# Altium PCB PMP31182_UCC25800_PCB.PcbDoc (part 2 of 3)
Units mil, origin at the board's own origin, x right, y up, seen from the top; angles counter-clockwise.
Board outline 4922 x 2266 mil, 4 copper layers (Top Layer, Signal Layer 1, Signal Layer 2, Bottom Layer), stack 77.9 mil thick; 172 components, 94 nets, 533 pads, 516 vias.
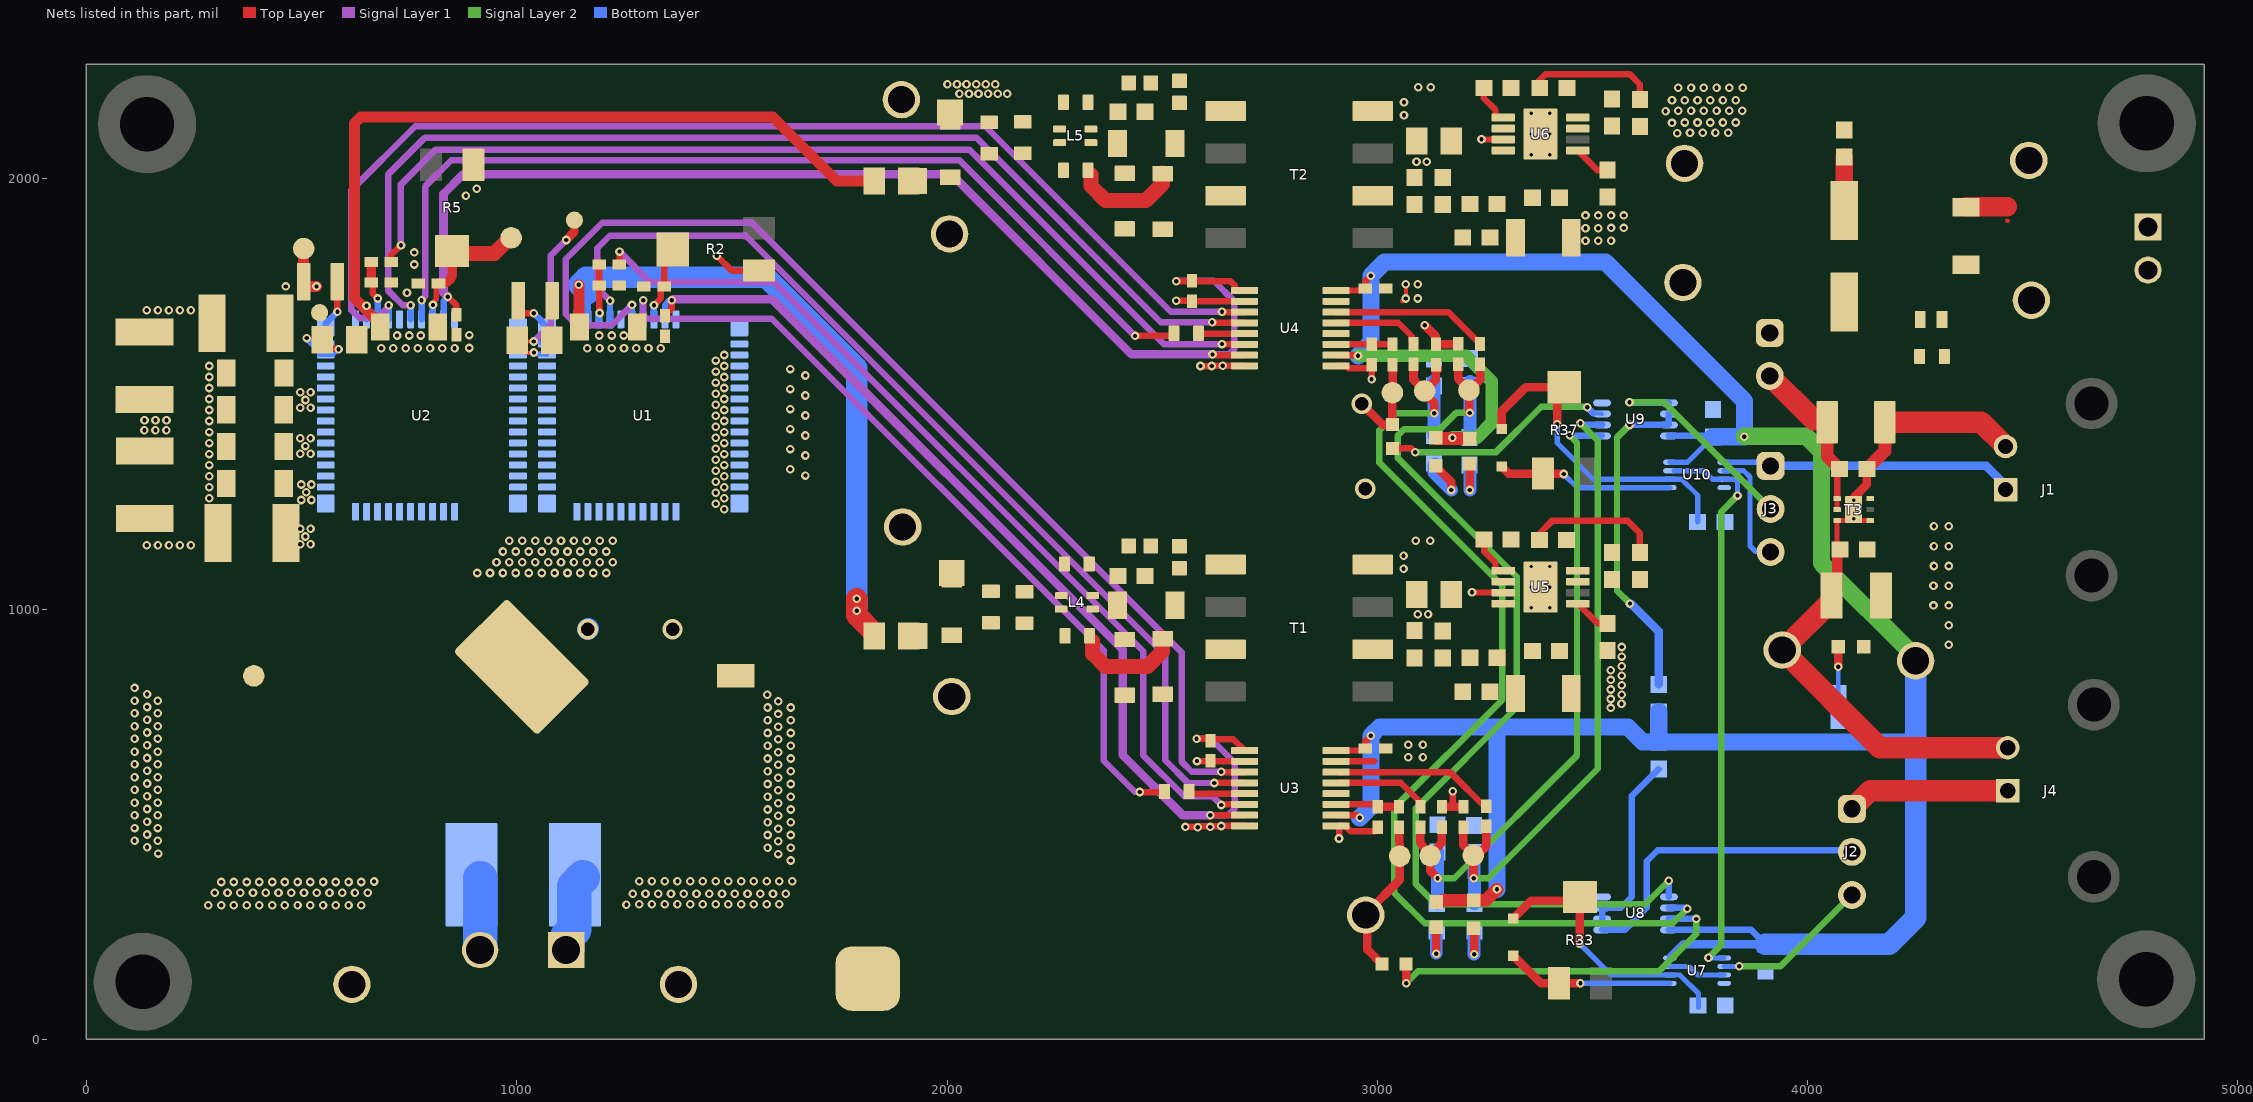
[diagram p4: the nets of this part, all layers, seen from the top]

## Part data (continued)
J7: library part CMP-0075405-2, "Header, 100mil, 2x1, Gold, TH", Color=Black, Current_A=6.3A, Manufacturer=Samtec, Supplier Part Number 1=SAM1029-02-ND, Voltage_V=550V
L1 L2: library part CMP-0090507-1, "4.7µH Shielded Molded Inductor 1.22A 262mOhm Max 1008 (2520 Metric)", Digikey Part Number=283-4799-1-ND, Manufacturer=Eaton, Mouser Part Number=704-MPIA2510V2-4R7-R, Operating Temperature Range="-40°C to +125°C", Self Resonant Frequency=25MHz, Test Frequency=1MHz, Tolerance_%=20%
L3: library part CMP-0060122-1, "Inductor, Wirewound, Ferrite, 240 nH, 0.85 A, 0.119999 ohm, SMD", Manufacturer=Coilcraft, PartNumber=0603AF-241KRB, Value1="0.119999 ohm", Value2=0.85A, ValueDisplayed=240nH
L4 L5: library part CMP-0090488-1, "2 Line Common Mode Choke Surface Mount 90 Ohms @ 100MHz 400mA DCR 190mOhm", Digikey Part Number=445-15969-1-ND, Impedance At Frequency="90Ω @ 100MHz", Manufacturer=TDK, Mouser Part Number=810-ACM20129002PT001, Operating Temperature Range="-40°C to +105°C"
LOGO1 LOGO3: library part CMP-0074837-1, "IEC 61010-1 Hot Surface Warning"
LOGO2 LOGO4: library part CMP-0074835-1, "IEC 61010-1 High Voltage Warning"
Logo6: library part CMP-0074838-1, "Texas Instrument Corporate Signature"
Logo8: library part CMP-0074769-1
R1 R3: library part CMP-0020443-3, "RES, 0, 5%, 0.333 W, AEC-Q200 Grade 0, 0805", Manufacturer=Vishay-Dale, Power_W=333mW, Supplier Part Number 1=541-0.0TBCT-ND, TempCo="200 ppm/C", Tolerance_%=5%, Value2=0.333W, Value_Code=0000, ValueDisplayed=0
R2 R5: library part CMP-0002064-2, "Trimmer, 200 K, 0.25 W, SMD", Manufacturer=Bourns, Supplier Part Number 1=3224X-1-204ECT-ND
R4 R8 R18 R26 R27 R41 R43: library part CMP-0089143-1, "0 Ohms Jumper 0.1W, 1/10W Chip Resistor 0603 (1608 Metric) Automotive AEC-Q200 Thick Film", Digikey Part Number=P0.0GCT-ND, Manufacturer=Panasonic, Mouser Part Number=667-ERJ-3GEY0R00V, Operating Temperature Range="-55°C to +155°C", Power_W=100mW, TempCo=-100/+600ppm/°C, Tolerance_%=5%
R6 R15 R19 R20 R39 R40: library part CMP-0026902-3, "RES, 300, 5%, 0.063 W, AEC-Q200 Grade 0, 0402", Manufacturer=Vishay-Dale, Power_W=63mW, Supplier Part Number 1=541-300JCT-ND, TempCo="200 ppm/C", Tolerance_%=5%, Value2=0.063W, Value_Code=300R, ValueDisplayed=300
R7 R16: library part CMP-0026404-2, "RES, 49.9, 1%, 0.063 W, AEC-Q200 Grade 0, 0402", Manufacturer=Vishay-Dale, Power_W=63mW, Supplier Part Number 1=541-49.9LCT-ND, TempCo="100 ppm/C", Tolerance_%=1%, Value2=0.063W, Value_Code=49R9, ValueDisplayed=49.9
R9 R24 R28 R32: library part CMP-0023630-3, "RES, 100 k, 0.1%, 0.1 W, 0603", Manufacturer="Yageo America", Power_W=100mW, Supplier Part Number 1=603-RT0603BRD07100KL, TempCo="25 ppm/C", Tolerance_%=0.1%, Value2=0.1W, Value_Code=100k
R10 R12 R14 R17 R21: library part CMP-0025797-4, "RES, 3.3 k, 5%, 0.1 W, AEC-Q200 Grade 0, 0603", Manufacturer=Vishay-Dale, Power_W=100mW, Supplier Part Number 1=541-3.3KGCT-ND, TempCo="200 ppm/C", Tolerance_%=5%, Value2=0.1W, Value_Code=3k30, ValueDisplayed=3.3k
R11 R29: library part CMP-0023990-3, "RES, 24.9 k, 0.1%, 0.1 W, 0603", Manufacturer="Yageo America", Power_W=100mW, TempCo="25 ppm/C", Tolerance_%=0.1%, Value2=0.1W, Value_Code=24k9, ValueDisplayed=24.9k
R13: library part CMP-0022714-3, "RES, 0.33, 1%, 0.1 W, AEC-Q200 Grade 0, 0603", Manufacturer=Panasonic, Power_W=100mW, Supplier Part Number 1=P.33AJCT-ND, TempCo="300 ppm/C", Tolerance_%=1%, Value2=0.1W, Value_Code=R330, ValueDisplayed=0.33
R22 R30: library part CMP-0024096-3, "RES, 30.1 k, 0.1%, 0.1 W, 0603", Manufacturer="Yageo America", Power_W=100mW, TempCo="25 ppm/C", Tolerance_%=0.1%, Value2=0.1W, Value_Code=30k1, ValueDisplayed=30.1k
R23 R31: library part CMP-0024954-2, "RES, 22.9 k, 0.5%, 0.1 W, 0603", Manufacturer="Yageo America", Power_W=100mW, TempCo="50 ppm/C", Tolerance_%=0.5%, Value2=0.1W, Value_Code=22k9, ValueDisplayed=22.9k
R25 R42: library part CMP-0023343-3, "RES, 0, 1%, 0.1 W, AEC-Q200 Grade 0, 0603", Manufacturer="Stackpole Electronics Inc", Power_W=100mW, Supplier Part Number 1=RMCF0603ZT0R00CT-ND, TempCo=ppm/C, Tolerance_%=1%, Value2=0.1W, Value_Code=0
R33 R37: library part CMP-0002062-2, "Trimmer, 5 K, 0.25 W, SMD", Manufacturer=Bourns, Supplier Part Number 1=3224X-1-502ECT-ND
R34 R38: library part CMP-0025697-4, "RES, 0, 5%, 0.1 W, AEC-Q200 Grade 0, 0603", Manufacturer=Vishay-Dale, Power_W=100mW, Supplier Part Number 1=541-0.0GCT-ND, TempCo="200 ppm/C", Tolerance_%=5%, Value2=0.1W, Value_Code=0000, ValueDisplayed=0
R35 R36: library part CMP-0082530-1, "RES, 100 k, 5%, 0.1 W, 0603", Manufacturer=Vishay-Dale, Power_W=100mW, Supplier Part Number 1=541-3992-1-ND, TempCo="200 ppm/C", Tolerance_%=5%, Value2=0.1W, Value_Code=100k
SH-J1 SH-J2 SH-J3: library part CMP-0003623-3, "Shunt, 100mil, Gold plated, Black", Alternate Manufacturer=3M, Alternate PartNumber=969102-0000-DA, Manufacturer=Samtec, Supplier Part Number 1=SAM8858-ND
T1 T2: library part CMP-0091345-1, "Transformer, 1:1.67, 0.045Ohm Pri, 0.122Ohm Sec, 16.5uH", Frequency_Fixed=500kHz, Manufacturer="Wurth Electronics", Operating Temperature Range="-40°C to +125°C", Part Number=750319177r02
T3: library part CMP-0086086-2, "150-mA High-Voltage Ultralow-IQ Low-Dropout Regulator, DRV0006A (WSON-6)", Alternate Manufacturer="Texas Instruments"
Top_FET_PWM: library part CMP-0055144-1, "Test Point, Compact, White, TH", Color=White, Manufacturer=Keystone, Supplier Part Number 1=36-5007-ND
TP1: library part CMP-0055153-1, "Test Point, Compact, SMT", Manufacturer=Keystone, Supplier Part Number 1=36-5016TR-ND
TP2: library part CMP-0003968-1, "Test Point, SMT", Manufacturer=Harwin, Supplier Part Number 1=952-2664-1-ND
U1 U2: library part CMP-0089968-1, "650-V 30-mΩ GaN FET with Integrated Driver and Protection", Manufacturer="Texas Instruments", Max Supply Voltage=18V, Min Supply Voltage=7.5V, Nominal Supply Current=540uA, Operating Temperature Range="-40°C to +125°C", Output Voltage=520V
U3 U4: library part CMP-0090469-1, "General Purpose Digital Isolator 2500Vrms 4 Channel 100Mbps 85kV/µs CMTI 16-SSOP (0.154\", 3.90mm Width)", Digikey Part Number=296-51207-1-ND, Manufacturer="Texas Instruments", Max Supply Voltage=5.5V, Min Supply Voltage=2.25V, Mouser Part Number=595-ISO7741FQDBQRQ1, Nominal Supply Current=1.5-18mA, Operating Temperature Range="-40°C to +125°C"
U5 U6: library part CMP-0088494-2, "Open Loop LLC Transformer Driver for Isolated Bias Supplies", Manufacturer="Texas Instruments", Max Supply Voltage=36V, Min Supply Voltage=12V, Nominal Supply Current=500uA, Operating Temperature Range="-40°C to +150°C", Switching Frequency=100-2000kHz
U7 U10: library part CMP-0051969-2, "Triple Schmitt-Trigger Inverter, DCU0008A (VSSOP-8)", F @ Nom Voltage(Max)(Mhz)=150, Generic Part Number=SN74LVC3G14, ICC @ Nom Voltage(Max)(mA)=0.01, Manufacturer="Texas Instruments", Operating Temperature Range="-40 to 125 C", Rating=Catalog, tpd @ Nom Voltage(Max)(ns)=9.2,5.7,5.4,4.3, Voltage(Nom)(V)=1.8,2.5,3.3,5
U8 U9: library part CMP-0051803-1, "Automotive Catalog Dual 2-Input Positive-AND Gate, DCT0008A, LARGE T&R", F @ Nom Voltage(Max)(Mhz)=150, Generic Part Number=SN74LVC2G08-Q1, ICC @ Nom Voltage(Max)(mA)=0.01, Manufacturer="Texas Instruments", Operating Temperature Range(C)="-40 to 85", Rating=Automotive, tpd @ Nom Voltage(Max)(ns)=9,5.1,4.7,3.8, Voltage(Nom)(V)=1.8,2.5,3.3,5

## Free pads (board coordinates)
  round 50 smd paste-30: 1(389,845) 1(505,1838) 1(987,1863) 1(3035,1503) 1(3052,426) 1(3110,1507) 1(3123,427) 1(3213,1509) 1(3223,428)
  round 40 smd paste-30: 1(542,1689) 1(1134,1904)
  round 228.35 hole 125.98: 2(131,134) 2(141,2127) 2(4787,140) 2(4788,2129)
  rect 60x60 smd: 3(1923,1995) 3(1925,938) 3(2007,2154) 3(2011,1084)
  rrect50% 150x150 smd: Load_GND(1816.25,141.5)

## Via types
v1: diameter 20, hole 10, Top Layer to Bottom Layer, tented both sides, 498 vias
v2: diameter 19.68, hole 7.87, Top Layer to Bottom Layer, 14 vias
v3: diameter 47.24, hole 31.5, Top Layer to Bottom Layer, 4 vias

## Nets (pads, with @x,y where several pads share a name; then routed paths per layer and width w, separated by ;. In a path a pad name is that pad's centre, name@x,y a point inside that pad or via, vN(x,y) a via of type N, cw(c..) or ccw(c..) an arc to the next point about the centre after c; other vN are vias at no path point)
5V: C9.1 C26.1 C41.2 C44.2 C48.1 C53.1 HS_FLT.1 HS_OC.1 LDO5V.1 LDO.1 LS_FLT.1 LS_OC.1 R35.1 R36.2 T3.6 U3.10 U3.16 U4.10 U4.16 U7.8 U8.8 U9.8 U10.8 | length 6821.8
  Top Layer w15: U3.10@2904.08,521.5 2952.5,521.5 v1(2959,515) ; U3.16@2904.08,671.5 2967.88,671.5 C26.1@2972.38,676 2972.38,693.38 v1(2985,706) ; U4.16@2904.33,1740.75 U4.16@2904.08,1740.5 2962.26,1740.5 C9.1@2969.57,1747.81 ; U4.10@2905.08,1590.5 2905.65,1589.93 2954.07,1589.93 v1(2955,1589) ; C9.1@2972.57,1744.81 2972.57,1762.57 v1(2985,1775)
  Top Layer w30: HS_FLT.1@3137,319.53 3137.75,320.28 3148.03,320.28 3151.24,323.48 HS_OC.1@3224,323.48 3252.48,323.48 v1(3278,349) ; LS_OC.1@3137.95,1396.53 v1@3172.57,1396.53 ; v1@3176.48,1396.53 LS_FLT.1@3215,1396.53
  Signal Layer 2 w30: v1@2956,1590 v1(2955,1589) 3206,1589 3266,1529 3266,1433 3231.48,1398.48 v1(3174.52,1398.48)
  Signal Layer 2 w40: v1(3853,1401) 3854,1402 3997,1402 4032,1367 4032,1107 4251,888 LDO5V.1@4251,880
  Bottom Layer w10: 4045.91,221.5 4045.91,221.65
  Bottom Layer w12: U10.8@3680.02,1341.37 3720.87,1341.37 C44.2@3780,1400.5
  Bottom Layer w15: U8.8@3677.76,254.61 3868.88,254.61 C41.2@3902,221.5 ; U9.8@3677.76,1402.61 C44.2@3777.89,1402.61
  Bottom Layer w20: R35.1@3654,693.5 3660.7,693.5 R35.1@3662.7,691.5 ; U7.8@3683.74,193.26 3711.98,221.5 C41.2@3902,221.5 ; 4245.5,691.5 4251,697
  Bottom Layer w40: v1(2955,1589) 2985,1619 v1(2985,1775) 3017,1807 3530,1807 3853,1484 v1(3853,1401) ; v1(2959,515) 2985,541 v1@2985,701.41 ; v1(2985,706) 3005,726 3278,726 ; v1(3278,349) 3278,726 ; R35.1@3654,691.5 3616.5,691.5 3582,726 3278,726 ; R35.1@3654,693.5 R36.2@3654,761.5 ; R35.1@3662.7,691.5 4245.5,691.5 ; C44.2@3780,1400.5 v1@3852.5,1400.5
  Bottom Layer w50: C41.2@3902,221.5 4045.91,221.5 4189.5,221.5 4251,283 4251,697 LDO5V.1@4251,880
  other v1: 4328,917.08 4328,962.91 4292.48,1008.75 4328,1008.75 4292.48,1054.58 4328,1054.58 4293.48,1100.41 4328,1100.41 4293.48,1146.46 4328,1146.46 4293.48,1192.46 4328,1192.46
5V_H: C2.1 C10.1 U1.51 U3.1 U3.7 | length 2474.7
  Top Layer w10: C10.1@2610.62,699 C10.1@2612,697.62
  Top Layer w15: C2.1@1344.59,1681.62 1344.59,1685.56 1348.9,1689.87 1351.67,1689.87 1360.45,1698.66 v1(1360.45,1718.06) ; v1(2580,699) C10.1@2610.62,699 ; C10.1@2612,697.62 2665.36,697.62 U3.1@2691.48,671.5 ; v1@2612.5,521.5 U3.7@2691.48,521.5
  Signal Layer 1 w15: v1(2580,699) 2613.08,699 2669,643.08 2669,537 2653,521 v1(2612,521)
  Signal Layer 1 w20: v1(1360.45,1718.06) 1362.37,1719.97 1369.44,1719.97 1594,1720 2408,906 2408,661 2548,521 v1(2612,521)
  Bottom Layer w15: U1.51@1344.59,1673.4 1344.59,1706.59 1355.1,1717.1 1359.5,1717.1 v1(1360.45,1718.06)
5V_L: C12.1 C27.1 U2.51 U4.1 U4.7 | length 2893.2
  Top Layer w15: v1(840,1726) 860,1706 C12.1@860,1684.62 ; v1(2533,1762) C27.1@2567.76,1762 ; C27.1@2573.5,1762 2658.7,1762 2669.13,1751.57 2669.13,1741.07 2669.7,1740.5 U4.1@2691.48,1740.5 ; v1(2617,1592) 2618.35,1592 2619.85,1590.5 U4.7@2691.48,1590.5
  Signal Layer 1 w15: v1@2533,1763 2620,1763 2668,1715 2668,1605.01 2654.99,1592 v1(2617,1592)
  Signal Layer 1 w20: v1(840,1726) 830,1736 830,1965 876,2011 2010,2011 2429,1592 v1(2617,1592)
  Bottom Layer w15: U2.51@830.17,1673.4 830.17,1716.17 v1(840,1726)
15V: 15VIN.1 C25.1 J6.2 L3.1 R8.1
15V_F: 15VINF.1 C7.1 C8.1 C24.1 C28.1 C29.1 C58.1 C59.1 C61.1 C62.1 J7.1 L3.2 R8.2 R9.2 R28.2 U5.8 U6.8
Bot_FET_FAULT: C52.1 C57.1 pad.1@3213,1509 R14.1 R40.2 U8.5 | length 2427.9
  Top Layer w20: C57.1@3188,1569.38 3188,1535.24 3204.07,1517.24 pad.1@3206.97,1514.34 ; pad.1@3213,1509 3214,1508 3214,1457 v1(3215,1456) ; pad.1@3215,1510.85 3239,1533 R40.2@3239,1569
  Signal Layer 2 w15: v1(3215,1456) 3183,1456 3145.49,1418.49 3062.49,1418.49 3047,1403 3047,1352 3324,1075 3324,772 3089,537 3089,361.5 3136.5,314 3622.38,314 v1@3677.19,368.81
  Bottom Layer w10: v1(3677,369) v1@3677.38,368.62 ; U8.5@3677.38,331.76 U8.5@3677.76,331.39
  Bottom Layer w15: U8.5@3677.38,331.76 v1@3677.38,368.62
  Bottom Layer w30: R14.1@3215,1398.5 v1(3215,1456) C52.1@3215,1529.5
Bot_FET_OC: C55.1 C56.1 pad.1@3110,1507 R17.1 R39.2 U8.6 | length 2553.9
  Top Layer w20: R39.2@3084,1569 3084,1533 pad.1@3110,1507 ; v1(3132,1455) 3132,1479.73 3110,1501.73 pad.1@3110,1507 ; C56.1@3140.7,1557.02 C56.1@3136,1568.38 3136,1533 pad.1@3110,1507
  Signal Layer 2 w15: v1(3132,1455) 3044,1455 3005,1416 3005,1340 3290,1055 3290,789 3039,538 3039,341 3110,270 3686,270 v1(3720,304)
  Bottom Layer w12: v1@3716.04,305.8 3717.84,304 v1(3720,304)
  Bottom Layer w15: U8.6@3677.76,305.8 v1@3716.04,305.8
  Bottom Layer w30: C55.1@3131,1530.5 3132,1529.5 v1(3132,1455) R17.1@3132,1403
Bot_FET_PWM: pad.1@3035,1503 R16.1 R38.2 | length 230.1
  Top Layer w20: v3(2964,1477) 3012,1429 R38.2@3035,1429 pad.1@3035,1503 3035.5,1537.5 R16.1@3035.5,1568.26
Bot_FET_TEMP: U4.12
FAULT_H: U1.46 U3.4 | length 2361.7
  Top Layer w10: U3.4@2705.23,595.25 U3.4@2706.48,596.5
  Top Layer w15: v1@2621.5,596.5 U3.4@2691.48,596.5
  Signal Layer 1 w15: v1(1217,1717) 1187,1747 1187,1839 1216,1868 1532,1868 2507,893 2507,649 2560,596 v1(2621,596)
  Bottom Layer w15: U1.46@1216.64,1673.4 1216.82,1673.58 1216.82,1712.82 v1@1217,1713
FAULT_L: U2.46 U4.3 | length 2734.9
  Top Layer w15: v1@2639.5,1690.5 U4.3@2691.48,1690.5
  Signal Layer 1 w15: v1(702.21,1706) 702.21,1704.65 699.71,1702.15 699.71,1700.07 675.65,1676 635,1676 616,1695 616,1974 764,2122 2089,2122 2520,1691 v1(2639,1691)
  Bottom Layer w15: U2.46@702.21,1673.4 v1(702.21,1706)
GND_HV: C11.1 C12.2 C13.1 C15.2 C16.2 C17.2 C18.2 C19.2 C20.2 C21.2 C23.1 C27.2 C38.2 C43.1 C49.2 C63.2 C64.2 D5.2 GNDHV.1 ISO15VGND.1 J5.1 L2.1 L5.1 pad.1@505,1838 pad.3@2007,2154 pad.Load_GND R5.1 R43.2 TP2.1 U2.17 U2.18 U2.19 U2.20 U2.21 U2.22 U2.23 U2.24 U2.25 U2.26 U2.27 U2.28 U2.29 U2.30 U2.31 U2.32 U2.33 U2.34 U2.35 U2.36 U2.37 U2.38 U2.39 U4.2 U4.8 | length 629.7
  Top Layer w10: C20.2@453,1138.74 C20.2@453,1159 ; pad.1@504.63,1834.63 pad.1@505,1835
  Top Layer w15: v1(2533,1717) C27.2@2562.19,1717 ; C27.2@2569.5,1715.5 U4.2@2691.48,1715.5 ; v1(2589,1565) v1(2615,1565) 2615.5,1565.5 2640.5,1565.5 v1(2641,1566) ; v1@2641.5,1565.5 U4.8@2691.48,1565.5
  Top Layer w25: pad.1@505,1835 504.63,1824.63 L2.1@504.63,1761 504.63,1750 v1(534.63,1750)
  Bottom Layer w10: C49.2@1109.47,344 C49.2@1148.47,383
  Bottom Layer w80: J5.1@1115,208 1117.32,210.32 1117.32,238.4 1133.57,254.64 1133.57,356.57 C49.2@1154,377
  other v1: 1255,313 1284.62,314 1314.23,314 1343.85,314 1373.46,314 1403.08,314 1432.69,314 1462.31,314 1491.92,314 1521.54,314 1551.15,314 1580.77,314 1610.38,314 1269.81,339 1299.42,339 1329.04,339 1358.65,339 1388.27,339 1417.88,339 1447.5,339 1477.11,339 1506.73,339 1536.34,339 1565.96,339 1595.57,339 1625.19,339 1284.62,368 1314.23,368 1343.85,368 1373.46,368 1403.08,368 1432.69,368 1462.31,368 1491.92,368 1521.54,368 1551.15,368 1580.77,368 1610.38,368 1640,368 1637,416 1608,430.81 1583,445.62 1637,445.62 1608,460.43 1583,475.23 1637,475.23 1608,490.04 1583,504.85 1637,504.85 1608,519.66 1583,534.46 1637,534.46 1608,549.27 1583,564.08 1637,564.08 1608,578.89 1583,593.69 1637,593.69 1608,608.5 1583,623.31 1637,623.31 1608,638.12 1583,652.92 1637,652.92 1608,667.73 1583,682.54 1637,682.54 1608,697.35 1583,712.15 1637,712.15 1608,726.96 1583,741.77 1637,741.77 1608,756.58 1583,771.38 1637,771.38 1608,786.19 1582,801 497,1150.87 521,1150.87 509,1168.87 497,1186.87 521,1186.87 499,1253.64 523,1253.64 511,1271.64 499,1289.64 523,1289.64 497,1361 521,1361 509,1379 497,1397 521,1397 134.82,1416 160.41,1416 186,1416 135,1439 160.59,1439 186.18,1439 497,1468 521,1468 509,1486 497,1504 521,1504 685,1606 713.43,1606 741.86,1606 770.29,1606 798.71,1606 827.14,1606 855.57,1606 890,1607 722,1636 750,1636 777,1636 890,1637 745,1735 463,1750 762,1801 762,1829 882,1961 907,1977 2028.84,2197.79 2051.04,2197.79 2073.24,2197.79 2095.44,2197.79 2117.64,2197.79 2139.84,2197.79 2001,2220 2023.2,2220 2045.4,2220 2067.6,2220 2089.8,2220 2112,2220
  other v3: 1362.2,953
GND_LV: C6.2 C7.2 C9.2 C14.1 C25.2 C26.2 C28.2 C29.2 C34.2 C36.2 C39.2 C40.2 C41.1 C44.1 C45.2 C46.2 C47.2 C48.2 C50.2 C51.2 C52.2 C53.2 C54.1 C55.2 C56.2 C57.2 C58.2 C61.2 C62.2 C67.2 C69.2 GND_LV.1 GNDLV.1 GNDLVF.1 J1.2 J4.2 J6.1 R13.1 R21.1 R22.1 R23.1 R24.1 R25.1 R30.1 R31.1 R32.1 R42.1 T3.3 T3.4 T3.7@4107,1231.35 U3.9 U3.15 U4.9 U4.15 U5.6 U5.9 U6.6 U6.9 U7.4 U8.4 U9.4 U10.4 | length 2933.8
  Top Layer w10: U3.9@2904.08,496.5 2907.93,496.5 U3.9@2911,493.43 ; C14.1@2986,1568.26 C14.1@2986.63,1567.63 ; C6.2@3001,489.56 C6.2@3001,493.5 ; 3057.8,1715.5 3064.29,1722 v1(3066,1722) 3067,1722 3066.5,1722.5 3066.5,1754.5 v1(3066,1755) ; 3175,543.97 3178.35,540.62 ; C48.2@4051.91,1035.63 C48.2@4055.91,1031.63 C48.2@4055.91,1019.91 ; C53.2@4068.61,1145.52 C53.2@4075.5,1138.63 ; T3.7@4103.06,1205.76 v2(4107,1209.69) T3.7@4110.94,1205.76 ; v2(4107,1253) T3.7@4113.95,1253 ; 4464.07,1902.93 4465,1902
  Top Layer w12: C53.2@4068.61,1145.52 T3.3@4068.61,1205.76 T3.7@4103.06,1205.76 ; T3.7@4110.94,1205.76 T3.4@4145.39,1205.76
  Top Layer w15: U3.15@2904.08,646.5 2993,646.5 ; U4.9@2904.08,1565.5 2927.5,1565.5 2933,1560.01 2981.69,1560.01 2986,1564.32 C14.1@2986,1568.26 ; U3.9@2907.93,496.5 2927.5,496.5 2928.08,495.93 2928.08,493.79 2937.86,484 2995.44,484 C6.2@3001,489.56 ; v1(2911,467) U3.9@2911,493.43 ; v1(2986.63,1534) C14.1@2986.63,1567.63 ; 3175,543.97 v1(3175,577) ; R31.1@3374.5,2204.93 3374.5,2226.63 3391.37,2243.5 3586.5,2243.5 3610,2220 C67.2@3610,2184.5 ; R23.1@3377.5,1153 3377.5,1176.5 3406,1205 3582,1205 3610,1177 C34.2@3610,1131.5
  Top Layer w20: v1(3110,1660) 3110.37,1660 3136,1634.37 C56.2@3136,1615.62 3187,1615.62 C57.2@3188,1616.62 ; C40.2@3150,540.62 3178.35,540.62 C39.2@3200,540.62 ; T3.7@4107,1231.35 v2(4107,1253) 4107,1259.01 4137.5,1289.5 C47.2@4137.5,1325.63
  Top Layer w25: C48.2@4055.91,1031.63 4069,1044.72 4069,1132.43 4075.2,1138.63 C53.2@4075.5,1138.63
  Top Layer w30: C47.2@4137.5,1325.63 4179.35,1367.49 C54.1@4179.35,1434.63
  Top Layer w45: C25.2@4368,1934.93 4464.07,1934.93
  Top Layer w50: C48.2@4055.91,1019.91 GND_LV.1@3941,905 4168,678 J4.2@4465,678 ; C54.1@4179.35,1434.63 4403.37,1434.63 J1.2@4460,1378
  other v1: 3072,656 3106,656 3072,685 3106,685 3542.48,770.54 3567.48,780.54 3542.79,791.16 3568,801 3542.79,813.36 3568,823.2 3542.79,835.56 3568,845.4 3542.79,857.76 3568,867.6 3568,889.8 3568,912 3094,988.02 3118,988 3089,1159 3123,1159 3094,1722 3094,1755 3483.73,1856.5 3513.49,1856.5 3543.24,1856.5 3483.73,1885.5 3513.49,1885.5 3543.24,1886 3573,1886 3483.73,1915 3513.49,1915 3543.24,1915 3573,1915 3091,2040.02 3115,2040 3696.92,2106 3726.54,2107 3756.15,2107 3785.77,2107 3815.38,2107 3684.73,2130 3714.35,2131 3743.96,2131 3773.58,2131 3803.19,2131 3832.81,2131 3669.92,2157 3699.54,2158 3729.15,2158 3758.77,2158 3788.38,2158 3818,2158 3848,2158 3684.73,2183 3714.35,2183 3743.96,2183 3773.58,2183 3803.19,2183 3832.81,2183 3699.54,2212 3729.15,2212 3758.77,2212 3788.38,2212 3818,2212 3849,2212 3095,2213 3124,2213
  other v2: 3357.73,1003.17 3401.04,1003.17 3357.73,1051.2 3401.04,1051.2 3357.73,1099.24 3401.04,1099.24 3357.73,2056.17 3401.04,2056.17 3357.73,2104.2 3401.04,2104.2 3357.73,2152.24 3401.04,2152.24
  other v3: 2972,1280
HVBUS: C15.1 C16.1 C17.1 C18.1 C19.1 C20.1 C21.1 C38.1 C49.1 HVIN.1 J5.2 pad.1@389,845 U1.1 U1.2 U1.3 U1.4 U1.5 U1.6 U1.7 U1.8 U1.9 U1.10 U1.11 U1.12 U1.13 U1.14 U1.15 U1.16 | length 169.8
  Bottom Layer w10: C49.1@907.53,383 C49.1@909.47,381.06
  Bottom Layer w80: J5.2@915,208 C49.1@915,375.06
  other v1: 283.5,312 313.12,312 342.73,312 372.35,312 401.96,312 431.58,312 461.19,312 490.81,312 520.42,312 550.04,312 579.65,312 609.27,312 638.88,312 298.31,341 327.92,341 357.54,341 387.15,341 416.77,341 446.38,341 476,341 505.62,341 535.23,341 564.85,341 594.46,341 624.08,341 653.69,341 313.12,366 342.73,366 372.35,366 401.96,366 431.58,366 461.19,366 490.81,366 520.42,366 550.04,366 579.65,366 609.27,366 638.88,366 668.5,367 167,432 141,446.81 112,461.62 166,461.62 141,476.42 112,491.23 166,491.23 141,506.04 112,520.85 166,520.85 141,535.65 112,550.46 166,550.46 141,565.27 112,580.08 166,580.08 141,594.88 112,609.69 166,609.69 141,624.5 112,639.31 166,639.31 141,654.11 112,668.92 166,668.92 141,683.73 112,698.54 166,698.54 141,713.34 112,728.15 166,728.15 141,742.96 112,757.77 166,757.77 141,772.57 112,787.38 166,787.38 141,802.19 112,817 140.59,1148.52 166.18,1148.52 191.77,1148.52 217.36,1148.52 242.95,1148.52 1482.43,1232.46 1462.43,1245.05 285.22,1258.05 1482.43,1258.05 1462.43,1270.64 285.22,1283.64 1482.43,1283.64 1462.43,1296.23 285.22,1309.23 1482.43,1309.23 1462.43,1321.82 285.22,1334.82 1482.43,1334.82 1462.43,1347.41 285.22,1360.41 1482.43,1360.41 1462.43,1373 285.22,1386 1482.43,1386 1462.43,1398.59 285.22,1411.59 1482.43,1411.59 1462.43,1424.18 285.22,1437.18 1482.43,1437.18 1462.43,1449.77 285.22,1462.77 1482.43,1462.77 1462.43,1475.36 285.22,1488.36 1482.43,1488.36 1462.43,1500.95 285.22,1513.95 1482.43,1513.95 1462.43,1526.54 285.22,1539.54 1482.43,1539.54 1462.43,1552.13 285.22,1565.13 1482.43,1565.13 1462.43,1577.73 1482.43,1590.73 140.59,1694.48 166.18,1694.48 191.77,1694.48 217.36,1694.48 242.95,1694.48
IN_H: C5.2 R6.2 U1.45 | length 116.5
  Top Layer w15: C5.2@1190.39,1749.38 1191.99,1747.78 1191.99,1688.78 v1(1192.6,1688.17) ; C5.2@1191.38,1752 R6.2@1191.38,1791
  Bottom Layer w15: U1.45@1191.05,1673.4 1191.05,1686.62 v1(1192.6,1688.17)
IN_L: C23.2 R15.2 U2.45 | length 139.7
  Top Layer w15: C23.2@661.47,1758.91 665.41,1754.97 665.41,1733.59 v1(677,1722)
  Top Layer w22: C23.2@661.47,1758.91 R15.2@661.47,1807
  Bottom Layer w15: U2.45@676.62,1673.4 v1@676.62,1721.62
ISO_15V_H: C30.1 C31.1 D2.1 ISO15VH.1 L4.2 pad.3@1925,938 R1.1 R4.2
ISO_15V_H_B: C22.2 C32.1 C33.1 D1.1 L4.3 R4.1 | length 250.6
  Top Layer w35: R4.1@2338.61,926.02 2338.61,896.39 2368,867 2466,867 2501,902 D1.1@2501,933.93
ISO_15V_L: C63.1 C64.1 D5.1 ISO15VL.1 L5.2 pad.3@1923,1995 R3.1 R27.2
ISO_15V_L_B: C60.2 C65.1 C66.1 D4.1 L5.3 R27.1 | length 248.7
  Top Layer w35: R27.1@2335,2010.54 2335,1983 2368,1950 2462.59,1950 2500.7,1988.12 D4.1@2500.7,2014.09
ISO_RET_H_B: C32.2 C33.2 C35.1 D3.2 L4.4 R26.1
ISO_RET_L_B: C65.2 C66.2 C68.1 D6.2 L5.4 R43.1
NC_PGND1: U2.43
NC_PGND2: U2.47
NC_PGND3: U2.52
NC_SW1: U1.43
NC_SW2: U1.47
NC_SW3: U1.52
NetC1_1: C1.1 R1.2 U1.44 | length 1588.9
  Top Layer w25: v1(1144,1754) 1145.07,1752.93 C1.1@1145.07,1656
  Top Layer w50: v1(1790,1024) v1(1790,996) 1790,985.5 1831,944.5 R1.2@1831,938
  Bottom Layer w15: U1.44@1165.46,1673.4 1165.46,1732.54
  Bottom Layer w50: 1165.46,1732.54 v1(1144,1754) 1161,1771 1580,1771 1790,1561 v1(1790,1024) v1@1790,1003
NetC6_1: C6.1 R7.2 U3.11 | length 149.7
  Top Layer w15: U3.11@2904.08,546.5 2996.69,546.5 3001,542.19 C6.1@3001,540.75
  Top Layer w20: C6.1@3001,540.75 R7.2@3050.5,540.75
NetC8_2: C8.2 C36.1 R9.1 R24.2 T1.3
NetC11_2: C11.2 R3.2 U2.44 | length 1807.5
  Top Layer w25: C11.2@683.03,1656 683.03,1665.84 672.38,1676.5 669.18,1676.5 623,1722.68 623,2129.36 637.64,2144 1595,2144 1744,1995 R3.2@1831,1995
  Bottom Layer w15: U2.44@651.03,1673.4 v1@651.03,1705
  other v1: 651.03,1705.08
NetC14_2: C14.2 R16.2 U4.11 | length 132.4
  Top Layer w15: U4.11@2904.08,1615.5 C14.2@2987,1615.5 ; C14.2@2986,1615.5 R16.2@3035.5,1615.5
NetC22_1: C22.1 C35.2 T1.8
NetC24_2: C24.2 R13.2 | length 124.2
  Top Layer w40: C24.2@4085,1926.3 R13.2@4085,2050.5
NetC34_1: C34.1 R11.2 U5.3
NetC42_1: C42.1 R2.2 U1.50 | length 173.1
  Top Layer w15: v1(1319,1706.08) 1335,1722.08 C42.1@1335,1745.69 ; C42.1@1342.62,1750 1342.62,1816.02 R2.2@1362.61,1836
  Bottom Layer w15: U1.50@1319,1673.4 v1@1319,1706
NetC43_2: C43.2 pad.1@987,1863 R5.2 U2.50 | length 329.9
  Top Layer w12: v1@805.12,1708.79 807.11,1710.78 807.11,1714.22 813,1720.11 813,1751.76 C43.2@818.24,1757
  Top Layer w22: C43.2@818.24,1757 826.62,1757 ccw(c826.62,1780.38) 850,1780.38 R5.2@850,1827
  Top Layer w35: R5.2@850,1827 948.19,1827 984.19,1863 pad.1@987,1863
  Bottom Layer w15: U2.50@804.58,1673.4 v1@804.58,1706
  other v1: 805.58,1707.08
NetC45_1: C45.1 D11.1 R33.2 U7.6 | length 640.4
  Top Layer w20: D11.1@3316,281.31 3356.69,322 3461.61,322 R33.2@3470,330.39 ; v1(3470,223) 3470,322 R33.2@3470,330.39 ; R33.2@3471,331.39 R33.2@3470,330.39
  Bottom Layer w12: v1(3470,223) 3542.84,150.16 U7.6@3680.02,150.16 3702.84,150.16 3746.5,106.5 C45.1@3746.5,74
NetC46_1: C46.1 D12.1 R37.2 U10.6 | length 785.4
  Top Layer w20: D12.1@3289,1418.31 3289,1460 3344.89,1515.89 R37.2@3434.5,1515.89 3418,1499.39 v1(3418,1430)
  Bottom Layer w12: v1(3418,1430) 3418,1386 3502,1302 U10.6@3680.02,1302 3707,1302 3744.5,1264.5 C46.1@3744.5,1203
NetC47_1: C47.1 C54.2 J7.2 T3.1 T3.2 | length 395.7
  Top Layer w12: T3.2@4068.61,1231.35 T3.1@4068.61,1256.94
  Top Layer w15: T3.1@4068.61,1256.94 C47.1@4068.61,1319.74
  Top Layer w20: C54.2@4040.13,1440 C54.2@4045.5,1434.63 ; C47.1@4068.61,1319.74 C47.1@4074.5,1325.63
  Top Layer w30: C54.2@4045.5,1434.63 4045.5,1354.64 C47.1@4074.5,1325.63
  Top Layer w50: J7.2@3912,1542 4014,1440 C54.2@4040.13,1440
NetC59_2: C59.2 C69.1 R28.1 R32.2 T2.3
NetC60_1: C60.1 C68.2 T2.8
NetC67_1: C67.1 R29.2 U6.3
NetD1_2: D1.2 D3.1 T1.6
NetD4_2: D4.2 D6.1 T2.6
NetD11_2: D11.2 R33.1 U7.5 | length 390.9
  Top Layer w20: D11.2@3316,194.69 3380.09,130.61 R33.1@3421.79,130.61 3471.61,130.61 v1(3472,131)
  Bottom Layer w12: v1(3472,131) 3472.53,130.47 U7.5@3680.02,130.47
NetD12_2: D12.2 R37.1 U10.5 | length 411.5
  Top Layer w20: D12.2@3289,1331.69 3305.59,1315.11 R37.1@3385.29,1315.11 3431.89,1315.11 v1(3433,1314)
  Bottom Layer w12: v1(3433,1314) 3464.68,1282.32 U10.5@3680.02,1282.32
NetHS_FLT_2: HS_FLT.2 R10.2 | length 113.4
  Top Layer w20: v1(3137,199) HS_FLT.2@3137,260.47
  Bottom Layer w10: R10.2@3137,251.5 R10.2@3138,252.5
  Bottom Layer w30: v1@3137,201 R10.2@3137,251.5
NetHS_OC_2: HS_OC.2 R12.2 | length 115.9
  Top Layer w10: HS_OC.2@3224,258.52 HS_OC.2@3225,257.52
  Top Layer w20: v1(3225,198) HS_OC.2@3225,257.52
  Bottom Layer w10: R12.2@3225,251.5 R12.2@3226,252.5
  Bottom Layer w30: v1(3225,198) R12.2@3225,251.5
NetJ2_2: J2.2 U8.1 | length 722.5
  Bottom Layer w15: U8.1@3522.24,254.61 3574.61,254.61 3626,306 3626,414 3652,440 4099,440 J2.2@4103,436
NetJ2_3: J2.3 U7.2 | length 365.8
  Signal Layer 2 w15: v1(3841,170) 3937,170 J2.3@4103,336
  Bottom Layer w10: v1@3840.84,169.84 v1(3841,170)
  Bottom Layer w12: U7.2@3806,169.84 v1@3840.84,169.84
NetJ3_2: J3.2 U9.5 | length 523.2
  Signal Layer 2 w15: v1(3586,1481) 3665.98,1481.02 J3.2@3914,1233
  Bottom Layer w15: v1(3586,1481) 3587.35,1481 3588.97,1479.39 U9.5@3677.76,1479.39
NetJ3_3: J3.3 U10.2 | length 280.2
  Bottom Layer w12: U10.2@3806,1321.69 3851.32,1321.69 3866,1307 3866,1146.45 3878.52,1133.93 3913.07,1133.93 J3.3@3914,1133
NetL1_2: L1.2 U1.42 | length 102.3
  Top Layer w15: L1.2@1003.63,1710 1003.63,1691.07 1007,1687.7 v1(1039.87,1687.7)
  Bottom Layer w15: v1(1039.87,1687.7) 1057.41,1670.16 1057.41,1667.87 U1.42@1070.58,1654.7
NetL2_2: L2.2 U2.42 | length 106.6
  Top Layer w15: v1(583.37,1691) L2.2@583.37,1750
  Bottom Layer w15: U2.42@556.15,1654.7 556.15,1663.78 v1(583.37,1691)
NetLDO_2: LDO.2 R21.2 | length 108.9
  Top Layer w20: v1(4071,866) LDO.2@4071,913
  Bottom Layer w10: v1(4071,866) 4071,805.5 R21.2@4072,804.5
NetLS_FLT_2: LS_FLT.2 R14.2 | length 121.8
  Top Layer w10: LS_FLT.2@3213,1335.47 LS_FLT.2@3215,1337.47
  Top Layer w20: v1(3215,1277) LS_FLT.2@3215,1337.47
  Bottom Layer w30: v1(3215,1277) R14.2@3215,1335.5
NetLS_OC_2: LS_OC.2 R17.2 | length 156.3
  Top Layer w10: LS_OC.2@3135,1332.52 LS_OC.2@3136,1333.52
  Top Layer w20: LS_OC.2@3135,1332.52 3137,1332.52 3141.75,1327.77 3141.75,1325.77 3172,1295.52 v1(3172,1277)
  Bottom Layer w10: R17.2@3132,1340.01 R17.2@3135,1337.01
  Bottom Layer w30: R17.2@3135,1337.01 3133.31,1335.32 3132,1335.32 3132,1317 v1(3172,1277)
NetR6_1: R6.1 U3.6 | length 2158.1
  Top Layer w10: R6.1@1238.62,1801 R6.1@1239,1801.38 ; U3.6@2706.23,546.25 U3.6@2706.48,546.5
  Top Layer w15: R6.1@1239,1801.38 v1(1239,1831) ; v1(2637,545) 2638.35,545 2639.85,546.5 U3.6@2691.48,546.5
  Signal Layer 1 w15: v1(1239,1831) 1310,1760 1598,1760 2456,902 2456,660 2551,565 2617,565 v1(2637,545)
NetR11_1: R11.1 R23.2 U5.4
NetR15_1: R15.1 U4.6 | length 2370.8
  Top Layer w15: R15.1@708.72,1807 708.72,1823.72 v1(731,1846) ; v1(2639,1616) 2639.25,1615.75 2691.23,1615.75 U4.6@2691.48,1615.5
  Signal Layer 1 w15: v1(731,1846) 731,1987 812.09,2068.09 2051.58,2068.09 2503.68,1616 v1(2639,1616)
NetR18_1: R18.1 U3.5 | length 130.8
  Top Layer w10: R18.1@2562.54,576 R18.1@2567.04,571.5
  Top Layer w15: R18.1@2567.04,571.5 U3.5@2691.48,571.5
NetR19_1: R19.1 U3.13 | length 225.7
  Top Layer w15: U3.13@2908.52,596.5 3054.5,596.5 3100,551 R19.1@3100,535.62
NetR20_1: R20.1 U3.14 | length 379.4
  Top Layer w15: U3.14@2908.52,621.5 3168.74,621.5 R20.1@3253,537.24
NetR22_2: R22.2 U5.5 | length 97.6
  Top Layer w15: R22.2@3248.49,1159 3248.49,1133.87 3274.66,1107.7 3274.66,1090.95 3276.02,1089.59 U5.5@3292.77,1089.59
NetR25_2: R25.2 U5.1 | length 88
  Top Layer w15: U5.1@3466,1012.82 3511.83,966.99 R25.2@3535,966.99
NetR29_1: R29.1 R31.2 U6.4
NetR30_2: R30.2 U6.5 | length 97
  Top Layer w15: R30.2@3247.5,2211 3247.5,2187.5 3274.66,2160.35 3274.66,2143.95 3276.02,2142.59 U6.5@3292.77,2142.59
NetR34_1: R34.1 U8.7 | length 862.4
  Top Layer w20: v1(3067,131) R34.1@3067,175
  Signal Layer 2 w15: v1(3067,131) 3095,159 3655,159 3741,245 v1@3741,278.1
  Bottom Layer w12: v1@3736.73,280.2 3738.84,278.1 v1@3741,278.1
  Bottom Layer w15: U8.7@3677.76,280.2 v1@3736.73,280.2
  other v1: 3741,280.1
NetR35_2: R35.2 U8.2 U8.3 | length 428.4
  Bottom Layer w15: U8.2@3522.24,280.2 U8.3@3522.24,305.8 3565.8,305.8 3591.5,331.5 3591.5,566.01 R35.2@3654,628.5
NetR36_1: R36.1 U9.6 U9.7 | length 773.3
  Signal Layer 2 w15: v1(3586,1428) 3557,1399 3557,1043 v1(3587,1013)
  Bottom Layer w15: v1(3586,1428) 3586.2,1428.2 U9.7@3677.76,1428.2 U9.6@3677.76,1453.8
  Bottom Layer w20: v1(3587,1013) 3589,1013 3654,948 R36.1@3654,825.48
NetR38_1: R38.1 U9.3 | length 541.7
  Top Layer w15: R38.1@3035,1373 3036,1374 3078.62,1374 3087.62,1365 v1(3088,1365)
  Signal Layer 2 w15: v1(3088,1365) 3276,1365 3381.1,1470.1 3487.08,1470.1 v1(3487.75,1469.43)
  Bottom Layer w10: U9.3@3502.28,1454.9 3521.14,1454.9 U9.3@3522.24,1453.8
  Bottom Layer w15: v1(3487.75,1469.43) U9.3@3502.28,1454.9
NetR39_1: R39.1 U4.13 | length 208.4
  Top Layer w15: U4.13@2904.08,1665.5 3048.5,1665.5 3079.69,1634.31 3079.69,1620.56 R39.1@3084,1616.24
NetR40_1: R40.1 U4.14 | length 365.7
  Top Layer w15: U4.14@2904.08,1690.5 3164.74,1690.5 R40.1@3239,1616.24
NetR41_2: R41.2 U2.49 | length 2242.1
  Top Layer w10: R41.2@2521.46,1635 R41.2@2527.46,1641
  Top Layer w15: v1(2437,1635) R41.2@2521.46,1635
  Signal Layer 1 w15: v1(778.98,1718) 778.98,1719.35 787,1727.37 787,1982 848,2043 2029,2043 v1(2437,1635)
  Bottom Layer w15: U2.49@778.98,1673.4 v1@778.98,1711
NetR42_2: R42.2 U6.1 | length 87.8
  Top Layer w15: U6.1@3466,2065.82 3511.32,2020.5 R42.2@3535,2020.5
NetT1_1: T1.1 U5.7 | length 72.2
  Top Layer w15: v1(3220,1039) 3220.3,1038.7 3291.66,1038.7 U5.7@3291.95,1038.41
  other v1: 3061,1094 3061,1124
NetT2_1: T2.1 U6.7 | length 51.4
  Top Layer w15: v1@3242,2093 3243.35,2093 3244.94,2091.41 U6.7@3292.77,2091.41
  other v1: 3242,2092 3062,2148 3062,2178
NetU7_1: U7.1 U10.3 U10.7 | length 1317.3
  Signal Layer 2 w15: v1(3769.65,190) 3799,219.35 3799,1226 v1(3837,1264)
  Bottom Layer w12: U10.7@3689.76,1321.78 3759.22,1321.78 3778.91,1302.09 U10.3@3796.25,1302.09 ; v1@3770.12,189.53 U7.1@3806,189.53 ; U10.3@3806,1302 3829.97,1302 3837,1294.97 v1(3837,1264)
NetU7_3: U7.3 U7.7 | length 134.1
  Bottom Layer w12: U7.7@3680.02,169.84 3724.16,169.84 3743.84,150.16 U7.3@3806,150.16
OC_H: U1.48 U3.3 | length 2635
  Top Layer w15: v1@2637.5,621.5 U3.3@2691.48,621.5
  Signal Layer 1 w15: v1(1268,1707) 1221,1660 1139.1,1660 1114,1685.1 1114,1813 1199,1898 1547,1898 2545.02,899.98 2545.02,645.98 2569,622 v1(2637,622)
  Bottom Layer w15: U1.48@1267.82,1673.4 1267.82,1706.82 v1(1268,1707)
OC_L: U2.48 U4.4 | length 2573.2
  Top Layer w15: v1(2616,1667) 2617.35,1667 2618.85,1665.5 U4.4@2691.48,1665.5
  Signal Layer 1 w15: v1(753.39,1706.08) 735.42,1706.08 701,1740.5 701,2010 787,2096 2068,2096 2497,1667 v1(2616,1667)
  Bottom Layer w15: U2.48@753.39,1673.4 v1@753.39,1706
PWM_Bot: J1.1 J3.1 U10.1 | length 686.1
  Bottom Layer w12: U10.1@3806,1341.37 3905.63,1341.37 J3.1@3914,1333
  Bottom Layer w20: J3.1@3914,1333 4415,1333 4460,1288 J1.1@4460,1278
PWM_Top: J2.1 J4.1 | length 379.4
  Top Layer w50: J2.1@4103,536 4145,578 J4.1@4465,578
SW: C1.2 C2.2 C3.1 C5.1 C10.2 C30.2 C31.2 C42.2 D2.2 ISO15VSW.1 L1.1 L4.1 pad.3@2011,1084 R2.1 R26.2 TP1.1 U1.17 U1.18 U1.19 U1.20 U1.21 U1.22 U1.23 U1.24 U1.25 U1.26 U1.27 U1.28 U1.29 U1.30 U1.31 U1.32 U1.33 U1.34 U1.35 U1.36 U1.37 U1.38 U1.39 U2.1 U2.2 U2.3 U2.4 U2.5 U2.6 U2.7 U2.8 U2.9 U2.10 U2.11 U2.12 U2.13 U2.14 U2.15 U2.16 U3.2 U3.8 | length 364.1
  Top Layer w10: C10.2@2608.62,647 2612,650.38 C10.2@2615.88,646.5
  Top Layer w15: v1(1465.04,1821.04) 1499.3,1786.79 R2.1@1563.39,1786.79 ; v1(2554,494) v1@2582,494 ; v1(2581,647) C10.2@2608.62,647 ; v1(2583,493) 2583.96,493.96 2587.49,493.96 2588.54,495 2609.65,495 2609.69,494.96 2611.96,494.96 v1@2612,495 ; v1@2612.96,494.96 2616.49,494.96 2616.54,495 2631.46,495 2631.51,495.04 2635.96,495.04 v1(2637,496) ; C10.2@2615.88,646.5 U3.2@2691.48,646.5 ; v1@2637.5,496.5 U3.8@2691.48,496.5 ; U3.8@2706.23,496.75 U3.8@2706.48,496.5
  Bottom Layer w50: v3(1165.35,953) v3@1166.35,954
  other v1: 2612,494 908,1084 938,1084 968,1084 998,1084 1028,1084 1058,1084 1088,1084 1118,1084 1148,1084 1178,1084 1208,1084 953,1109 983,1109 1013,1109 1043,1109 1073,1109 1103,1109 1133,1109 1163,1109 1193,1109 1223,1109 968,1134 998,1134 1028,1134 1058,1134 1088,1134 1118,1134 1148,1134 1178,1134 1208,1134 983,1159 1013,1159 1043,1159 1073,1159 1103,1159 1133,1159 1163,1159 1193,1159 1223,1159 1671,1310.5 1636,1325.5 1671,1357 1636,1372 1671,1403.5 1636,1418.5 1671,1450 1636,1465 1671,1496.5 1636,1511.5 1671,1543 1636,1558 1164.14,1606 1192.57,1606 1221,1606 1249.43,1606 1277.86,1606 1306.29,1606 1334.71,1606 1192,1636 1221,1636 1249,1636
TEMP_H: R18.2 U1.49 | length 1900.2
  Top Layer w10: R18.2@2504.46,575 R18.2@2505.46,576
  Top Layer w15: v1(2448,575) R18.2@2504.46,575
  Signal Layer 1 w15: v1(1294,1718) 1294,1683.79 1302.79,1675 1593,1675 2364,904 2364,648 2436.04,575.96 2447.04,575.96 v1(2448,575)
  Bottom Layer w15: U1.49@1293.41,1673.4 1293.41,1717.41 v1(1294,1718)
TEMP_L: R41.1 U4.5 | length 99.4
  Top Layer w10: R41.1@2593.54,1637 R41.1@2597.04,1640.5
  Top Layer w15: R41.1@2597.04,1640.5 U4.5@2691.48,1640.5
Top_FET_FAULT: C40.1 C50.1 pad.1@3123,427 R10.1 R19.2 U9.1 | length 1587.3
  Top Layer w20: R19.2@3100,488.38 3100,456 pad.1@3123,427 ; v1(3140,375) 3123,392 pad.1@3123,427 ; C40.1@3150,488.38 3150,458 pad.1@3123,427
  Signal Layer 2 w15: v1(3140,375) 3179,375 3464,660 3464,1387 v1(3447,1404)
  Bottom Layer w10: v1(3447,1404) v1@3447.69,1403.31 ; U9.1@3521.55,1403.31 U9.1@3522.24,1402.61
  Bottom Layer w15: v1@3447.69,1403.31 U9.1@3521.55,1403.31
  Bottom Layer w30: R10.1@3140,317.5 v1(3140,375) C50.1@3140,436
Top_FET_OC: C39.1 C51.1 pad.1@3223,428 R12.1 R20.2 U9.2 | length 1583.6
  Top Layer w20: C39.1@3200,488.38 3200,451 pad.1@3223,428 ; v1(3224,375) 3223.5,375.5 3223.5,427.5 pad.1@3223,428 ; R20.2@3253,490 3253,449 3232,428 pad.1@3223,428
  Signal Layer 2 w15: v1(3224,375) 3258,375 3512,629 3512,1392 v1(3472,1432)
  Bottom Layer w15: v1(3472,1432) 3473.35,1432 3477.15,1428.2 U9.2@3522.24,1428.2
  Bottom Layer w30: v1@3225,376 C51.1@3225,434.5 ; R12.1@3226,315.5 v1@3226,373
Top_FET_PWM: pad.1@3052,426 R7.1 R34.2 Top_FET_PWM.1 | length 358.7
  Top Layer w20: R34.2@3011,175 2977,209 2977,296 3052,371 pad.1@3052,426 R7.1@3050.5,488.5
Top_FET_TEMP: U3.12
VNEG_H: C3.2 pad.1@1134,1904 U1.40 U1.41 | length 478.4
  Top Layer w10: C3.2@1001,1625 1001,1618.5 1024.11,1595.39 1038.93,1595.39 v1(1040,1596.46) ; C3.2@1004,1622 v1(1039.76,1622)
  Top Layer w20: v1(1115,1858) 1134,1877 pad.1@1134,1904
  Signal Layer 1 w15: v1(1039.76,1622) 1079,1661.24 1079,1822 v1(1115,1858)
  Bottom Layer w10: v1(1039.76,1622) 1052.1,1622 1057.78,1616.32 U1.41@1070.58,1616.32 ; v1(1040,1596.46) 1042.71,1596.46 1046.91,1592.26 1069.04,1592.26 U1.40@1070.58,1590.73
VNEG_L: C13.2 pad.1@542,1689 U2.40 U2.41 | length 147.3
  Top Layer w15: C13.2@549,1624 568,1605 v1@587,1605
  Bottom Layer w10: U2.40@541.28,1590.73 U2.40@556.15,1590.73 572.73,1590.73 v1@587,1605
  Bottom Layer w15: v1(512,1630) 525.69,1616.32 U2.41@556.15,1616.32
  other v1: 586,1604
pads on no net: J1.3 J1.4 J4.3 J4.4 R2.3 R5.3 R33.3 R37.3 SH-J1.0 SH-J2.0 SH-J3.0 T1.2 T1.4 T1.5 T1.7 T2.2 T2.4 T2.5 T2.7 T3.5 T3.7@4107,1213.63 T3.7@4107,1249.06 U5.2 U6.2

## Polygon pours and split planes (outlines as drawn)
GND_LV on Bottom Layer "Signal Layer 1-GND_LV" (solid, pour order 169): 3078,2226.13 3091,2238 3583,2238 3824,2238 3871,2191 3871,1597.06 3894.71,1574 4859,1574 4859,415 4466,22 3172,22 3110,84 3110,269 3005,374 3005,441 2900,441 2898,439 2898,490 2996.53,490 3008,501.47 3008,1242 2937,1242 2936,1241 2934,1243 2934,1310 2987,1310 3008,1331 3008,1487 2977,1518 2977,1743 3078,1844
GND_HV on Bottom Layer "GND_HV_L04_P000" (solid, remove dead copper, pour order 0): 900,1639 893,1646 786,1646 652,1646 580,1574 470,1574 450,1554 450,1154 470,1134 820,1134 900,1214
SW on Bottom Layer "SW_L04_P004" (solid, remove dead copper, pour order 4): 970.29,1674.3 970.29,1165.3 895,1090 895,1069 905,1059 1221,1059 1238.29,1076.29 1238.29,1175.29 1260.89,1197.89 1371,1198 1380,1207 1380,1246 1240,1386 1240,1450.84 1380,1590.84 1380,1636 1370,1646 1131,1646 1100,1615 1100,1583 1091,1574 1032,1574 1024,1582 1024,1673.77 1013.76,1684 980,1684
HVBUS on Bottom Layer "HVBUS_L04_P016" (solid, remove dead copper, pour order 16): 1534.06,1214 1540,1219.94 1540,1672.95 1535.95,1677 1473,1677 1450,1654 1450,1234 1470,1214
NetT1_1 on Signal Layer 2 "NETT1_1_L03_P147" (solid, pour order 147): 3247,1022 3252,1027 3252,1042 3154.93,1139.07 3049.07,1139.07 3043,1131 3043,1082 3050,1075 3153,1075 3206,1022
